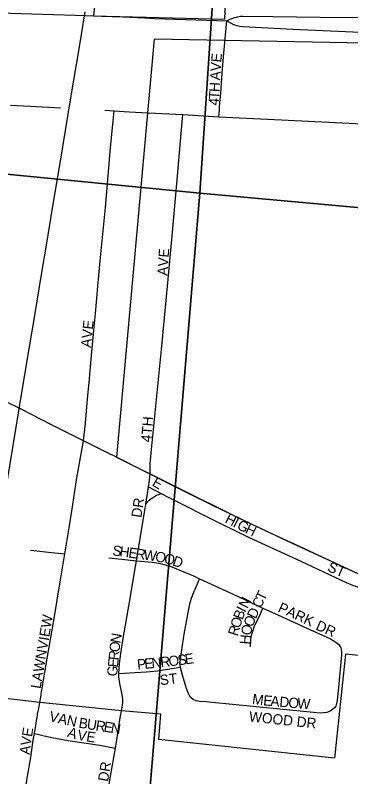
# Model space of a CAD drawing. Extents: x 1410790 to 1770854, y 566777 to 831614.
# Drawn here: x 1614218 to 1615859, y 699284 to 703004 of the extents above; entities that cross this region are included whole.
import ezdxf

# ---------------------------------------------------------------- set-up
doc = ezdxf.new("R2010")
doc.units = 0
for name, color, linetype in [('GM_X_City_Street', 7, 'Continuous'), ('GM_X_City_Street_Text', 7, 'Continuous'), ('GM_X_Corporation', 7, 'Continuous'), ('GM_X_Rail_Line', 7, 'Continuous'), ('GM_X_Section', 7, 'Continuous'), ('GM_X_State_Route', 7, 'Continuous'), ('GM_X_Township_Subdivision', 7, 'Continuous'), ('GM_X_Township_Subdivision_Text', 7, 'Continuous'), ('GM_X_US_Route', 7, 'Continuous')]:
    doc.layers.add(name, color=color, linetype=linetype)

msp = doc.modelspace()

# ---------------------------------------------------------------- linework, layer by layer
at = {"layer": 'GM_X_City_Street'}
for points in [[(1614195, 702565.2), (1614290.8, 702559.9), (1614439.8, 702552.4)], [(1614552.2, 700924.3), (1614561.3, 701010.9), (1614568.5, 701090.6), (1614573.5, 701146.4), (1614579.3, 701209.8), (1614584.6, 701267.4), (1614589.6, 701323.2), (1614593, 701360.3), (1614602.6, 701465.8), (1614610.2, 701546.8), (1614615.3, 701601.8), (1614622.7, 701680.8), (1614627.6, 701733), (1614634.2, 701803.9), (1614647, 701934.5), (1614659.1, 702064.7), (1614676.3, 702259.2), (1614683, 702340.5), (1614698.5, 702503.8), (1614701.7, 702537.3)], [(1614656, 702540), (1614701.7, 702537.3)], [(1614701.7, 702537.3), (1614774.9, 702532.8), (1614867.7, 702527.5)], [(1614460.2, 700372.3), (1614481.8, 700500), (1614495, 700580.7), (1614519.7, 700744.7), (1614547.3, 700897), (1614552.2, 700924.3)], [(1614869.6, 700699.8), (1614872.6, 700720.2), (1614877.7, 700762.1)], [(1614857, 700615), (1614869.6, 700699.8)], [(1614869.6, 700699.8), (1614894.2, 700687), (1614931.6, 700667.1)], [(1614857, 700615), (1614867.4, 700628.1), (1614873.9, 700634.8), (1614879.6, 700640.3), (1614888, 700646.4), (1614898.9, 700653.2), (1614909.9, 700659.3), (1614920, 700663.3), (1614931.6, 700667.1)], [(1614931.6, 700667.1), (1614966.7, 700649.3), (1615215.1, 700524.5), (1615361.9, 700452.7), (1615614.2, 700336.4), (1615836.7, 700233.2), (1615866.7, 700220.4), (1615881.9, 700215), (1615897.5, 700210.9), (1615913.6, 700210.1), (1615925.4, 700212), (1615934.7, 700214.8), (1615944.7, 700220.2), (1615956.8, 700228.4), (1615972.6, 700240.2)], [(1614811.1, 700338.9), (1614849.8, 700575.9), (1614857, 700615)], [(1614292.7, 700391.2), (1614309.8, 700388.9), (1614395.7, 700379.6), (1614460.2, 700372.3)], [(1614338.8, 699647.1), (1614343, 699672.1), (1614347.4, 699698.5), (1614374.4, 699861.2), (1614408.4, 700057.1), (1614437.7, 700236.8), (1614460.2, 700372.3)], [(1614676.3, 700353.2), (1614739.6, 700346.5), (1614811.1, 700338.9)], [(1614725.1, 699788.4), (1614727.6, 699837.1), (1614734.4, 699885.4), (1614744.3, 699949.7), (1614783.7, 700174.3), (1614805.2, 700302.8), (1614811.1, 700338.9)], [(1614811.1, 700338.9), (1614888.4, 700331.6), (1614920.9, 700326.7), (1614952.7, 700319.3), (1614983.9, 700309.3), (1615089.7, 700264.9), (1615120.1, 700250.8)], [(1615026.5, 699819.9), (1615025.2, 699828), (1615024.5, 699844.3), (1615025.8, 699860.6), (1615045.7, 699990.9), (1615066.5, 700103.1), (1615073.6, 700135), (1615082.1, 700161), (1615092.1, 700186.5), (1615109.5, 700226.4), (1615120.1, 700250.8)], [(1615120.1, 700250.8), (1615283.2, 700175.2), (1615429.8, 700108)], [(1615368.5, 699918.8), (1615370.4, 699952), (1615372.6, 699968.5), (1615376.2, 699984.7), (1615381.3, 700000.4), (1615387.4, 700015.8), (1615415.2, 700076.3), (1615429.8, 700108)], [(1615429.8, 700108), (1615506.4, 700072.9), (1615640.7, 700011.6), (1615760.1, 699957.6), (1615786.1, 699942.2), (1615800, 699930.8), (1615806.2, 699922.4), (1615808.6, 699916.8)], [(1615808.6, 699916.8), (1615809.6, 699914.7), (1615812.4, 699905.2), (1615814.2, 699893), (1615814, 699879.3), (1615799.5, 699720.3), (1615792.1, 699656.8), (1615789.1, 699641.4), (1615785.4, 699629.5), (1615780.2, 699621.1), (1615771.6, 699613.4)], [(1614725.1, 699788.4), (1614753.1, 699789.9), (1614803.6, 699792.9), (1614860.9, 699797), (1614914.1, 699802.1), (1614993.2, 699814.9), (1615026.5, 699819.9)], [(1615198.4, 699645.4), (1615197.1, 699645.5), (1615152, 699649.8), (1615119.3, 699652.2), (1615103.2, 699655.7), (1615088.2, 699661.9), (1615078.7, 699669.7), (1615072.6, 699677.5), (1615066.9, 699686.8), (1615060.5, 699702.7), (1615054.5, 699719.8), (1615035.5, 699779.9), (1615027.7, 699811.8), (1615026.5, 699819.9)], [(1614738, 699606.3), (1614744.1, 699643.7), (1614745, 699661), (1614743, 699676.8), (1614736.1, 699708.1), (1614729.9, 699739.8), (1614725.7, 699772.1), (1614725.1, 699788.4)], [(1615771.6, 699613.4), (1615757.7, 699604.5), (1615742.3, 699598.5), (1615726.1, 699595.8), (1615709.7, 699595.3), (1615660.1, 699598.8), (1615396, 699625.8), (1615264.1, 699638.6), (1615198.4, 699645.4)]]:
    msp.add_lwpolyline(points, dxfattribs=at)
at = {"layer": 'GM_X_Corporation'}
for points in [[(1614618.6, 703165.5), (1614600.8, 703000.9), (1615242.5, 702985), (1615288.1, 704103.9)], [(1615927.6, 702867.9), (1614897.7, 702887.8), (1614713.2, 700845.6), (1615310.3, 700548.7), (1615550.8, 700434.8), (1615847.5, 700297.7), (1615972.6, 700240.2)], [(1616305.8, 699835.5), (1615832.7, 699882.7), (1615779.1, 699374.7), (1614920.1, 699465.3), (1614931, 699590.3), (1614738, 699606.3), (1614338.8, 699647.1), (1613974.6, 699689), (1613706.5, 697548.1), (1615532, 697360.8), (1616779.5, 697219.4)]]:
    msp.add_lwpolyline(points, dxfattribs=at)
at = {"layer": 'GM_X_Rail_Line'}
msp.add_lwpolyline([(1613660.2, 697611.3), (1613756.8, 698189.3), (1613762.8, 698225.7), (1613816.6, 698552.5), (1613852, 698764.6), (1613897.7, 699037.2), (1613949, 699342.4), (1613974.5, 699500.6), (1614028, 699817.5), (1614066.2, 700052.9), (1614098.4, 700241.6), (1614144.5, 700515.3), (1614191.5, 700803.5), (1614239.3, 701090.6), (1614274, 701298.4), (1614314.4, 701537.4), (1614347, 701737.4), (1614371, 701881.5), (1614402.2, 702071.6), (1614437.6, 702281.5), (1614491, 702600.5), (1614533.2, 702850.1), (1614561.1, 703019.8)], dxfattribs=at)
at = {"layer": 'GM_X_Section'}
for points in [[(1610104.6, 708025.3), (1615479.9, 707495.5), (1615120.2, 702135.6), (1609553.2, 702682.3)], [(1615479.9, 707495.5), (1620745.4, 706937.6), (1620208.5, 701671.7), (1615120.2, 702135.6)], [(1609553.2, 702682.3), (1615120.2, 702135.6), (1614682.3, 696901), (1609051.7, 697468.6)], [(1615120.2, 702135.6), (1620208.5, 701671.7), (1619668.6, 696337.8), (1614682.3, 696901)]]:
    msp.add_lwpolyline(points, close=True, dxfattribs=at)
at = {"layer": 'GM_X_State_Route'}
for points in [[(1614552.2, 700924.3), (1614395.4, 701003.4), (1614247.9, 701078.9), (1614099.4, 701151.8), (1614032.6, 701185), (1613851.2, 701276), (1613631.5, 701387.1), (1613578, 701413.5), (1613338.1, 701532.9), (1613006.1, 701697.7), (1612927.1, 701738.9), (1612816.7, 701793.8), (1612767.2, 701819), (1612614.2, 701896.7), (1612354.1, 702026.6), (1612148, 702129.3), (1611849.9, 702278.1)], [(1614713.2, 700845.6), (1614713.2, 700845.6), (1614669.7, 700866.3), (1614577.7, 700911.4), (1614552.2, 700924.3)], [(1616020.5, 700218.2), (1616010.5, 700222.7), (1615972.6, 700240.2), (1615806.6, 700316.5), (1615583.7, 700419.5), (1615550.8, 700434.8), (1615420.5, 700495.1), (1615185, 700609.6), (1615065.6, 700667.9), (1615023.2, 700688.6), (1614877.7, 700762.1), (1614833.3, 700784.6), (1614713.2, 700845.6)]]:
    msp.add_lwpolyline(points, dxfattribs=at)
at = {"layer": 'GM_X_Township_Subdivision'}
for points in [[(1615213.5, 702508.2), (1615216.4, 702542.1), (1615217.8, 702558.3), (1615222.9, 702623.3), (1615230.7, 702720.5), (1615237.1, 702801.6), (1615252.6, 702975.9)], [(1614867.7, 702527.5), (1615038, 702519.3)], [(1614877.7, 700762.1), (1614878.4, 700805.6), (1614878.7, 700815.6), (1614880, 700828.7), (1614884.8, 700882.6), (1614904.3, 701078.5), (1614933, 701371.9), (1614965.9, 701715), (1614986.8, 701943.9), (1615000.1, 702091), (1615013.6, 702238.1), (1615034.9, 702483.2), (1615038, 702519.3)], [(1615038, 702519.3), (1615064.1, 702518.1), (1615213.5, 702508.2)], [(1615213.5, 702508.2), (1615245.7, 702506.1), (1615520.7, 702492.3), (1615916.2, 702473.7), (1616095.5, 702464.1), (1616226, 702457.4), (1616357.8, 702450.7), (1616469.4, 702445.6), (1616537.9, 702442.6), (1616702.1, 702434), (1616800.7, 702429), (1616879.8, 702424.9), (1616911, 702423.4)], [(1614312, 699495.9), (1614320.2, 699544.9), (1614322.4, 699558.1), (1614324.9, 699573.7), (1614327.6, 699589), (1614330.6, 699603.9), (1614333.3, 699617.6), (1614338.8, 699647.1)], [(1614707.9, 699424.2), (1614714.9, 699464.2), (1614730.2, 699561.6), (1614738, 699606.3)], [(1614064.6, 697907.6), (1614058.5, 697918.1), (1614054.9, 697933.5), (1614054.9, 697949.8), (1614056.1, 697965.9), (1614069, 698046.7), (1614087.6, 698143.3), (1614099.3, 698207.7), (1614113, 698288.4), (1614172.1, 698643.8), (1614190.6, 698755.7), (1614196.1, 698787.4), (1614228.3, 698980.8), (1614259.7, 699174.6), (1614279.2, 699287.4), (1614293.2, 699368), (1614306.6, 699463), (1614312, 699495.9)], [(1614312, 699495.9), (1614333.5, 699490.5), (1614360.5, 699484), (1614405.7, 699474.4), (1614486.3, 699460.3), (1614632.1, 699438.2), (1614680.4, 699429.2), (1614707.9, 699424.2)], [(1614641.4, 699030.3), (1614683.6, 699286.5), (1614707.9, 699424.2)]]:
    msp.add_lwpolyline(points, dxfattribs=at)
at = {"layer": 'GM_X_US_Route'}
for points in [[(1613372.9, 703024.7), (1613462.9, 703023.4), (1613554, 703023), (1613608.3, 703022.5), (1613819.9, 703018.9), (1613923.5, 703017.7), (1613969.5, 703017.3), (1614070.4, 703016.4), (1614194, 703013.5), (1614299.4, 703010.6), (1614510.7, 703003.7), (1614562.8, 703002.2), (1614600.8, 703000.9), (1614640.2, 702999.4)], [(1614640.2, 702999.4), (1614743.9, 702995.5), (1614851.3, 702990.8)], [(1614851.3, 702990.8), (1614901, 702988.6), (1615252.6, 702975.9)], [(1615252.6, 702975.9), (1615269.8, 702984.2), (1615286.6, 702991), (1615305.6, 702996.3), (1615319.2, 702998.8), (1615330.4, 702999.5), (1615477.2, 702998.2), (1615708.9, 702995.2), (1615912, 702992.3)], [(1615252.6, 702975.9), (1615270.3, 702966.2), (1615286.4, 702959.4), (1615302.4, 702953.8), (1615317.3, 702950.4), (1615329.4, 702948.9), (1615362.8, 702947.2), (1615576.3, 702935.7), (1615907.3, 702920.9)]]:
    msp.add_lwpolyline(points, dxfattribs=at)

# ---------------------------------------------------------------- texts
at = {"layer": 'GM_X_City_Street_Text'}
for s, rotation, p in [('AVE', 84.0899, (1614588.3, 701378.5)), ('E', 330.2568, (1614883.9, 700708.1)), ('DR', 81.4652, (1614834.8, 700547.2)), ('H', 332.6823, (1615240, 700527.9)), ('I', 332.6528, (1615279.1, 700507.7)), ('G', 332.6921, (1615298.7, 700497.6)), ('H', 333.5558, (1615338.5, 700477)), ('S', 352.1462, (1614691.3, 700366.1)), ('H', 352.1512, (1614726.1, 700361.3)), ('E', 352.1327, (1614769.7, 700355.3)), ('R', 352.1573, (1614804.6, 700350.4)), ('W', 352.1493, (1614843.9, 700345)), ('O', 349.003, (1614899.8, 700337.3)), ('O', 344.7602, (1614942, 700329.2)), ('D', 341.1123, (1614983.7, 700317.8)), ('ST', 336.8061, (1615741, 700290.6)), ('T', 64.1619, (1615435.9, 700139.1)), ('N', 63.4203, (1615352.7, 700102.7)), ('C', 64.1681, (1615418.6, 700103.5)), ('I', 63.4447, (1615342.9, 700083)), ('PARK', 335.5548, (1615499.2, 700092.5)), ('LAWNVIEW', 80.4166, (1614342, 699711.5)), ('B', 68.9067, (1615329.1, 700047.2)), ('D', 65.0676, (1615394.4, 700051.9)), ('O', 73.1689, (1615316.7, 700006)), ('O', 68.5882, (1615378.7, 700011.7)), ('DR', 336.0313, (1615683.9, 700004.5)), ('R', 73.174, (1615305.2, 699968.1)), ('O', 76.0486, (1615368.6, 699970.6)), ('N', 79.8046, (1614732.2, 699933.4)), ('H', 84.9668, (1615365, 699928.8)), ('O', 84.1317, (1614727.9, 699890.7)), ('R', 84.2425, (1614723.9, 699851.3)), ('E', 84.2255, (1614720.4, 699816.2)), ('P', 5.7187, (1614816.8, 699807.3)), ('E', 5.7329, (1614851.8, 699810.8)), ('N', 5.7258, (1614886.8, 699814.3)), ('R', 5.7154, (1614930.6, 699818.7)), ('O', 6.7439, (1614971, 699822.8)), ('S', 7.7186, (1615015.6, 699828.1)), ('E', 7.7554, (1615050.5, 699832.8)), ('G', 84.2415, (1614715.9, 699772.5)), ('ST', 7.1284, (1614928.4, 699730.7)), ('M', 352.7123, (1615374.8, 699639.8)), ('E', 354.9982, (1615429.4, 699632.9)), ('A', 355.1443, (1615464.6, 699629.8)), ('D', 355.1561, (1615508.4, 699626.1)), ('O', 355.1561, (1615552.3, 699622.4)), ('W', 355.1526, (1615596.1, 699618.7)), ('WOOD DR', 353.946, (1615359.6, 699554.6))]:
    msp.add_text(s, height=50, rotation=rotation, dxfattribs=at).set_placement(p)
at = {"layer": 'GM_X_Township_Subdivision_Text'}
for s, rotation, p in [('E', 84.7474, (1615225.4, 702772)), ('V', 86.6489, (1615222.9, 702728.5)), ('A', 86.6489, (1615220.3, 702684.6)), ('H', 86.6489, (1615217, 702627.5)), ('T', 86.6375, (1615214.9, 702592.4)), ('4', 86.6574, (1615213.1, 702561.6)), ('AVE', 86.0496, (1614962.3, 701730.2)), ('4TH', 85.4285, (1614883.1, 700916.3)), ('V', 347.3159, (1614381.3, 699556.6)), ('A', 347.3052, (1614424.3, 699547)), ('N', 347.3174, (1614467.2, 699537.3)), ('B', 350.5226, (1614526, 699524.2)), ('U', 351.2957, (1614565.8, 699517.5)), ('R', 351.2957, (1614609.3, 699510.9)), ('E', 80.8072, (1614300.1, 699476.6)), ('A', 341.6825, (1614469.9, 699480.9)), ('E', 351.296, (1614648.4, 699504.9)), ('N', 351.2908, (1614683.2, 699499.6)), ('V', 82.3707, (1614294.3, 699433.3)), ('V', 350.1095, (1614519.4, 699465.1)), ('E', 350.8635, (1614563.5, 699457.5)), ('A', 83.2301, (1614289.1, 699389.8)), ('DR', 81.0327, (1614672, 699258.2))]:
    msp.add_text(s, height=50, rotation=rotation, dxfattribs=at).set_placement(p)

doc.saveas('drawing.dxf')
